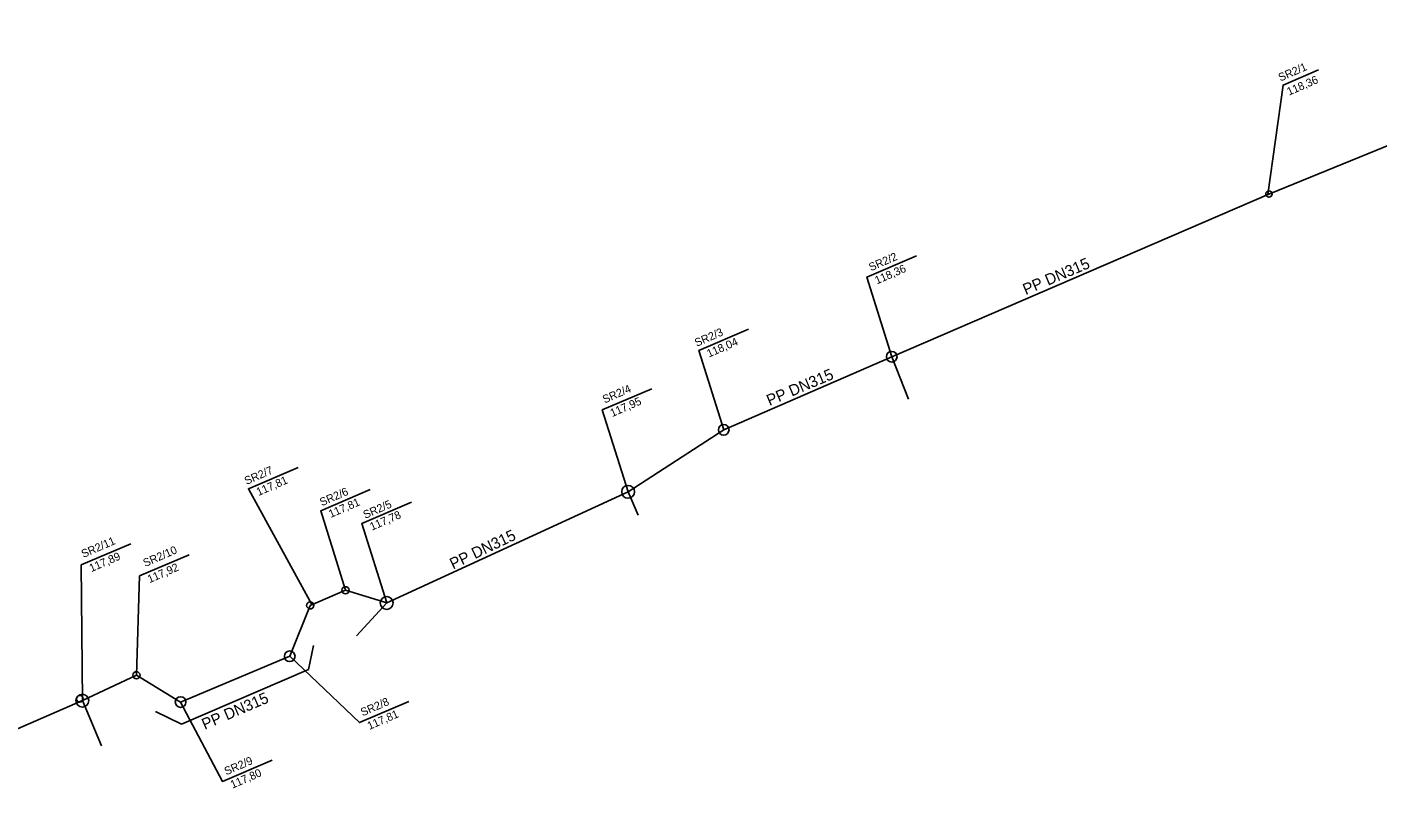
# Model space of a CAD drawing. Extents: x 7499288 to 7500494, y 5768505 to 5769051.
# Drawn here: x 7499762.8 to 7499889.5, y 5768710.1 to 5768783.3 of the extents above; entities that cross this region are included whole.
import ezdxf

# ---------------------------------------------------------------- set-up
doc = ezdxf.new("R2010")
doc.units = 0
for name, color, linetype in [('1_proj_kd_etap2', 7, 'Continuous'), ('1_proj_wodociąg', 7, 'Continuous'), ('2_opisy_KD_etap1', 7, 'Continuous')]:
    doc.layers.add(name, color=color, linetype=linetype)

msp = doc.modelspace()

# ---------------------------------------------------------------- linework, layer by layer
at = {"layer": '1_proj_kd_etap2'}
for p, q in [((7499917.59, 5768783.31), (7499879.26, 5768767.65)), ((7499843.9, 5768752.4), (7499879.26, 5768767.65)), ((7499828.15, 5768745.54), (7499843.9, 5768752.4)), ((7499845.47, 5768748.41), (7499843.9, 5768752.4)), ((7499819.19, 5768739.73), (7499828.15, 5768745.54)), ((7499796.56, 5768729.31), (7499819.19, 5768739.73)), ((7499820.13, 5768737.55), (7499819.19, 5768739.73)), ((7499789.39, 5768729.08), (7499792.7, 5768730.5)), ((7499792.7, 5768730.5), (7499796.56, 5768729.31)), ((7499787.47, 5768724.31), (7499789.39, 5768729.08)), ((7499793.72, 5768726.23), (7499796.56, 5768729.31)), ((7499777.24, 5768720.02), (7499787.47, 5768724.31)), ((7499768.03, 5768720.15), (7499773.1, 5768722.53)), ((7499773.1, 5768722.53), (7499777.24, 5768720.02)), ((7499744.91, 5768710.09), (7499768.03, 5768720.15)), ((7499769.82, 5768715.92), (7499768.03, 5768720.15))]:
    msp.add_line(p, q, dxfattribs=at)
for centre, radius in [((7499879.26, 5768767.65), 0.3), ((7499843.9, 5768752.4), 0.5), ((7499828.15, 5768745.54), 0.5), ((7499819.19, 5768739.73), 0.6), ((7499792.7, 5768730.5), 0.336), ((7499789.39, 5768729.08), 0.336), ((7499796.56, 5768729.31), 0.6), ((7499787.47, 5768724.31), 0.5), ((7499773.1, 5768722.53), 0.336), ((7499768.03, 5768720.15), 0.6), ((7499767.8, 5768720.33), 0.311), ((7499777.24, 5768720.02), 0.5)]:
    msp.add_circle(centre, radius, dxfattribs=at)
at = {"layer": '1_proj_wodociąg'}
for p, q in [((7499789.24, 5768723.07), (7499789.7, 5768725.31)), ((7499777.31, 5768717.95), (7499789.24, 5768723.07)), ((7499774.9, 5768719.14), (7499777.31, 5768717.95))]:
    msp.add_line(p, q, dxfattribs=at)
at = {"layer": '2_opisy_KD_etap1'}
for points in [[(7499883.9, 5768779.28), (7499880.58, 5768777.86), (7499879.15, 5768767.6)], [(7499846.22, 5768761.85), (7499841.57, 5768759.86), (7499843.9, 5768752.4)], [(7499830.47, 5768754.98), (7499825.82, 5768752.99), (7499828.15, 5768745.54)], [(7499821.41, 5768749.4), (7499816.76, 5768747.41), (7499819.19, 5768739.73)], [(7499788.26, 5768742.01), (7499783.6, 5768740.02), (7499789.55, 5768729.15)], [(7499795.02, 5768739.94), (7499790.37, 5768737.95), (7499792.7, 5768730.5)], [(7499798.88, 5768738.76), (7499794.22, 5768736.77), (7499796.56, 5768729.31)], [(7499772.59, 5768734.86), (7499767.93, 5768732.88), (7499768.03, 5768720.15)], [(7499778.04, 5768733.83), (7499773.39, 5768731.85), (7499773.1, 5768722.53)], [(7499798.65, 5768720.08), (7499794, 5768718.09), (7499787.47, 5768724.31)], [(7499785.82, 5768714.57), (7499781.16, 5768712.58), (7499777.24, 5768720.02)]]:
    msp.add_lwpolyline(points, dxfattribs=at)

# ---------------------------------------------------------------- texts
for s, height, rotation, p in [('SR2/1', 0.75, 23.5988, (7499880.34, 5768778.19)), ('118,36', 0.75, 23.5988, (7499881.14, 5768776.87)), ('SR2/2', 0.75, 23.5988, (7499841.95, 5768760.4)), ('118,36', 0.75, 23.5988, (7499842.51, 5768759.17)), ('PP DN315', 1.05, 22.9552, (7499856.46, 5768758.17)), ('SR2/3', 0.75, 23.5988, (7499825.62, 5768753.32)), ('118,04', 0.75, 23.5988, (7499826.76, 5768752.31)), ('PP DN315', 1.05, 22.9552, (7499832.44, 5768747.77)), ('SR2/4', 0.75, 23.5988, (7499816.99, 5768748.01)), ('117,95', 0.75, 23.5988, (7499817.7, 5768746.73)), ('SR2/7', 0.75, 23.5988, (7499783.42, 5768740.37)), ('117,81', 0.75, 23.5988, (7499784.54, 5768739.33)), ('SR2/6', 0.75, 23.5988, (7499790.48, 5768738.37)), ('117,81', 0.75, 23.5988, (7499791.31, 5768737.27)), ('SR2/5', 0.75, 23.5988, (7499794.55, 5768737.19)), ('117,78', 0.75, 23.5988, (7499795.17, 5768736.08)), ('SR2/11', 0.75, 23.5988, (7499768.13, 5768733.52)), ('PP DN315', 1.05, 25.5297, (7499802.78, 5768732.44)), ('117,89', 0.75, 23.5988, (7499768.87, 5768732.19)), ('SR2/10', 0.75, 23.5988, (7499773.92, 5768732.67)), ('117,92', 0.75, 23.5988, (7499774.33, 5768731.16)), ('PP DN315', 1.05, 23.2659, (7499779.5, 5768717.4)), ('SR2/8', 0.75, 23.5988, (7499794.31, 5768718.67)), ('117,81', 0.75, 23.5988, (7499794.94, 5768717.4)), ('SR2/9', 0.75, 23.5988, (7499781.53, 5768713.14)), ('117,80', 0.75, 23.5988, (7499782.1, 5768711.89))]:
    msp.add_text(s, height=height, rotation=rotation, dxfattribs=at).set_placement(p)

doc.saveas('drawing.dxf')
